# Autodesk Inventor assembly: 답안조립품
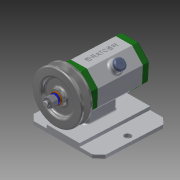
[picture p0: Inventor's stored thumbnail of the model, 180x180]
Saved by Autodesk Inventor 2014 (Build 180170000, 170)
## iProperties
Created: 2018-06
Part Number: 답안조립품
Document SubType Name: Assembly
Designer: kh
Author: kh
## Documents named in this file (16)
- C:\Users\kh\Desktop\480607V1008\답안조립품.iam
- C:\Users\kh\Desktop\480607V1008\답안본체.ipt
- C:\Users\kh\Desktop\480607V1008\V벨트풀리.ipt
- C:\Users\kh\Desktop\480607V1008\고무캡.ipt
- C:\Users\kh\Desktop\480607V1008\너트 M8.ipt
- 너트 M8.ipt
- C:\Users\kh\Desktop\480607V1008\뒤커버.ipt
- C:\Users\kh\Desktop\480607V1008\베어링 15x32x9.ipt
- C:\Users\kh\Desktop\480607V1008\볼트 M4x12.ipt
- C:\Users\kh\Desktop\480607V1008\스프링와셔 8.ipt
- C:\Users\kh\Desktop\480607V1008\앞커버.ipt
- C:\Users\kh\Desktop\480607V1008\오일 실 15 25 7.ipt
- C:\Users\kh\Desktop\480607V1008\와셔 8x17.ipt
- C:\Users\kh\Desktop\480607V1008\축.ipt
- C:\Users\kh\Desktop\480607V1008\키 3x3x12.ipt
- 키 3x3x12.ipt
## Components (2 placed, 2 different names)
1. V벨트풀리:1 — Insert:8, Mate:1, Insert:9
2. 고무캡:1 — Insert:20
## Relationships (4: Insert 3, Mate 1)
- Insert:8: V벨트풀리:1
- Mate:1: V벨트풀리:1
- Insert:9: V벨트풀리:1
- Insert:20: 고무캡:1
